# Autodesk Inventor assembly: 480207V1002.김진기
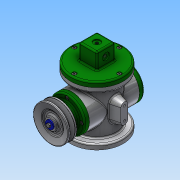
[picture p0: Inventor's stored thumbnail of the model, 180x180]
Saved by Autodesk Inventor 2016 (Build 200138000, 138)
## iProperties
Created: 2018-02
Part Number: 480207V1002.김진기
Material: 일반
Document SubType Name: Assembly
Designer: Administrator
Author: Administrator
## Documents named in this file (17)
- C:\Users\Administrator\Desktop\480207V1002.김진기\480207V1002.김진기.iam
- C:\Users\Administrator\Desktop\480207V1002.김진기\480207V1002.김진기.ipt
- C:\Users\Administrator\Desktop\480207V1002.김진기\뒤커버.ipt
- C:\Users\Administrator\Desktop\480207V1002.김진기\베어링 17 x 40 x 12.ipt
- C:\Users\Administrator\Desktop\480207V1002.김진기\앞커버.ipt
- C:\Users\Administrator\Desktop\480207V1002.김진기\오일 실 17 30 8.ipt
- C:\Users\Administrator\Desktop\480207V1002.김진기\덮개.ipt
- C:\Users\Administrator\Desktop\480207V1002.김진기\편심축.ipt
- C:\Users\Administrator\Desktop\480207V1002.김진기\V-벨트풀리.ipt
- C:\Users\Administrator\Desktop\480207V1002.김진기\키 4 x 4 x 12.ipt
- C:\Users\Administrator\Desktop\480207V1002.김진기\볼트 M4 x 10.ipt
- C:\Users\Administrator\Desktop\480207V1002.김진기\와셔 4x16.ipt
- C:\Users\Administrator\Desktop\480207V1002.김진기\링크.ipt
- C:\Users\Administrator\Desktop\480207V1002.김진기\슬라이더.ipt
- C:\Users\Administrator\Desktop\480207V1002.김진기\클레비스 핀 6 x 22.ipt
- 클레비스 핀 6 x 22.ipt
- C:\Users\Administrator\Desktop\480207V1002.김진기\볼트 M4 x 8.ipt
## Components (2 placed, 2 different names)
1. 480207V1002.김진기:1 — 각도:2, 각도:4
2. V-벨트풀리:1 — 각도:3
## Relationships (3: Angle 3)
- 각도:2 [Angle]: 480207V1002.김진기:1
- 각도:3 [Angle]: V-벨트풀리:1
- 각도:4 [Angle]: 480207V1002.김진기:1
